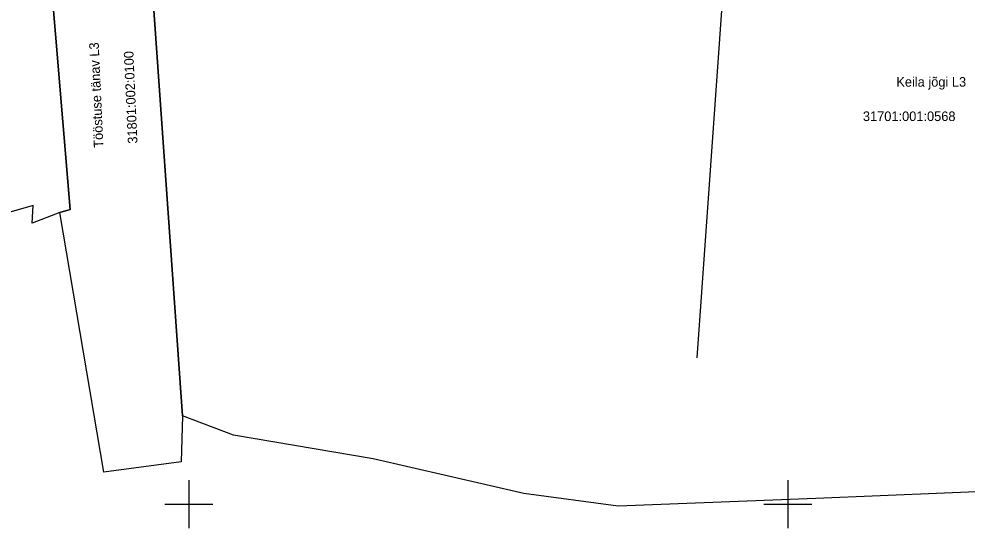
# Model space of a CAD drawing. Extents: x 542320 to 543602, y 6558748 to 6559969.
# Drawn here: x 542935.8 to 543015, y 6559748 to 6559790.5 of the extents above; entities that cross this region are included whole.
import ezdxf

# ---------------------------------------------------------------- set-up
doc = ezdxf.new("R2010")
doc.units = 0
for name, color, linetype in [('PIIR', 7, 'Continuous'), ('VORK', 7, 'Continuous'), ('VTRASS', 7, 'Continuous')]:
    doc.layers.add(name, color=color, linetype=linetype)

# ---------------------------------------------------------------- blocks, each defined once
blk = doc.blocks.new('VKORIS')
for p, q in [((0, 4), (0, -4)), ((-4, 0), (4, 0))]:
    blk.add_line(p, q)

msp = doc.modelspace()

# ---------------------------------------------------------------- linework, layer by layer
at = {"layer": 'PIIR'}
for points in [[(543002.19, 6559938.61), (542995.32, 6559882.88), (542984.27, 6559884.51), (542969.58, 6559880.67), (542959.71, 6559851.95), (542951.57, 6559852.97), (542950.23, 6559842.65), (542983.46, 6559838.42), (542982.04, 6559828.61), (542999.42, 6559826.35), (542995.62, 6559810.72), (542945.79, 6559811), (542937.03, 6559811.18), (542940.09, 6559774.59), (542939.23, 6559774.33), (542936.93, 6559773.44), (542936.99, 6559774.91), (542930.97, 6559773.19), (542914.12, 6559772.15), (542904.4, 6559772.44), (542898.6, 6559772.95), (542894.88, 6559773.72), (542892.18, 6559776.92)], [(542940.09, 6559774.59), (542937.03, 6559811.18), (542945.79, 6559811), (542946.49, 6559799.49), (542949.46, 6559757.36), (542949.37, 6559753.51), (542942.89, 6559752.66), (542939.23, 6559774.33), (542940.09, 6559774.59)], [(543023.83, 6559751.36), (543002.34, 6559750.46), (542985.84, 6559749.82), (542977.98, 6559750.87), (542965.4, 6559753.76), (542953.74, 6559755.74), (542949.46, 6559757.36), (542946.49, 6559799.49), (542966.22, 6559801.72), (543001.44, 6559800.31), (543012.82, 6559798.86), (543029.51, 6559799.26)]]:
    msp.add_lwpolyline(points, dxfattribs=at)
at = {"layer": 'VTRASS'}
msp.add_lwpolyline([(543002.613, 6559849.713), (542997.592, 6559829.35), (542995.798, 6559809.995), (542992.399, 6559762.213)], dxfattribs=at)

# ---------------------------------------------------------------- block references
at = {"layer": 'VORK', "xscale": 0.5, "yscale": 0.5}
for p in [(542950, 6559750), (543000, 6559750)]:
    msp.add_blockref('VKORIS', p, dxfattribs=at)

# ---------------------------------------------------------------- texts
at = {"layer": 'PIIR'}
for s, p in [('Tööstuse tänav L3', (542942.874, 6559779.746)), ('31801:002:0100', (542945.718, 6559780.089))]:
    msp.add_text(s, height=0.8, rotation=92.62422, dxfattribs=at).set_placement(p)
for s, p in [('Keila jõgi L3', (543009.065, 6559784.827)), ('31701:001:0568', (543006.273, 6559781.959))]:
    msp.add_text(s, height=0.8, dxfattribs=at).set_placement(p)

doc.saveas('drawing.dxf')
